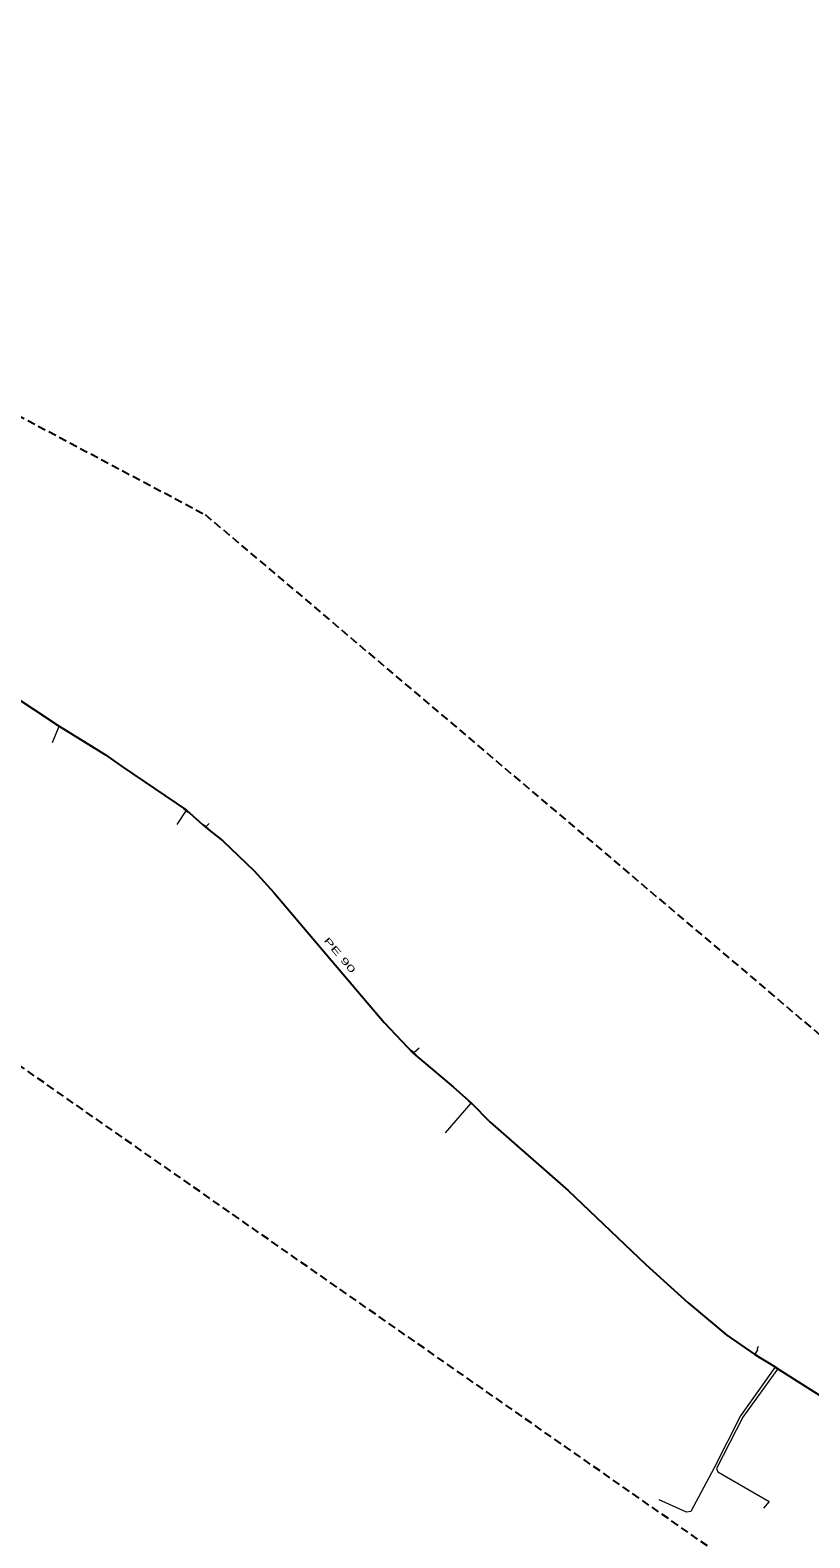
# Model space of a CAD drawing. Extents: x -692311 to -690519, y -971696 to -970899.
# Drawn here: x -692193.2 to -692075.2, y -971126.7 to -970898.7 of the extents above; entities that cross this region are included whole.
import ezdxf

# ---------------------------------------------------------------- set-up
doc = ezdxf.new("R2010")
doc.units = 0
doc.header["$LTSCALE"] = 0.4
doc.linetypes.add('MEDIUM_DASHED', pattern=[4.5, 3, -1.5])
for name, color, linetype, lineweight in [('1', 7, 'MEDIUM_DASHED', 25), ('13', 7, 'Continuous', 13), ('14', 7, 'Continuous', 13), ('17', 7, 'Continuous', 25), ('34', 7, 'Continuous', 13)]:
    doc.layers.add(name, color=color, linetype=linetype, lineweight=lineweight)

msp = doc.modelspace()

# ---------------------------------------------------------------- linework, layer by layer
at = {"layer": '1'}
msp.add_lwpolyline([(-691377.453, -971285.953), (-691463.283, -971177.096), (-691580.514, -971177.096), (-691632.849, -971177.096), (-691781.481, -971235.711), (-691971.982, -971202.217), (-692089.213, -971128.947), (-692311.114, -970974.035), (-692304.834, -970898.672), (-692166.669, -970971.942), (-691976.169, -971133.134), (-691904.993, -971149.882), (-691798.229, -971170.816), (-691674.718, -971116.387), (-691582.607, -971118.48), (-691415.135, -971114.294)], dxfattribs=at)
at = {"layer": '13'}
for p, q in [((-692188.818, -971003.998), (-692189.8, -971006.44)), ((-692169.574, -971016.731), (-692170.98, -971018.809)), ((-692166.541, -971019.127), (-692166.057, -971018.655)), ((-692135.115, -971053.309), (-692134.278, -971052.609)), ((-692126.47, -971060.966), (-692130.364, -971065.46))]:
    msp.add_line(p, q, dxfattribs=at)
for points in [[(-692083.441, -971098.909), (-692083.039, -971098.25), (-692083.1, -971098.079), (-692082.96, -971097.73)], [(-692080.498, -971100.92), (-692085.68, -971108.26), (-692089.66, -971116.09), (-692093.17, -971122.71), (-692093.87, -971122.829), (-692097.997, -971120.94)], [(-692080.061, -971101.184), (-692085.329, -971108.469), (-692089.329, -971116.19), (-692089.12, -971116.71), (-692081.34, -971121.219), (-692082.195, -971122.19)]]:
    msp.add_lwpolyline(points, dxfattribs=at)
at = {"layer": '14'}
for p, q in [((-692188.77, -971003.92), (-692188.818, -971003.998)), ((-692169.52, -971016.66), (-692169.574, -971016.731)), ((-692166.613, -971019.21), (-692166.541, -971019.127)), ((-692135.199, -971053.39), (-692135.115, -971053.309)), ((-692126.42, -971060.91), (-692126.47, -971060.966)), ((-692083.489, -971098.989), (-692083.441, -971098.909)), ((-692080.449, -971100.84), (-692080.498, -971100.92)), ((-692080.02, -971101.12), (-692080.061, -971101.184))]:
    msp.add_line(p, q, dxfattribs=at)
at = {"layer": '17'}
msp.add_lwpolyline([(-692200.44, -970996.21), (-692188.77, -971003.92), (-692181.73, -971008.289), (-692179.17, -971010.07), (-692169.52, -971016.66), (-692166.613, -971019.21), (-692164.02, -971021.3), (-692159.239, -971025.829), (-692156.289, -971029.1), (-692148.42, -971038.35), (-692139.583, -971048.749), (-692135.199, -971053.39), (-692129.1, -971058.52), (-692126.42, -971060.91), (-692123.559, -971063.84), (-692111.75, -971074.19), (-692100.01, -971085.37), (-692093.62, -971091.149), (-692087.739, -971096.03), (-692083.489, -971098.989), (-692080.449, -971100.84), (-692080.02, -971101.12), (-692073.59, -971105.23)], dxfattribs=at)
at = {"layer": '34'}
for p, q in [((-692188.392, -971004.261), (-692189.242, -971003.733)), ((-692169.176, -971017.034), (-692169.97, -971016.426)), ((-692166.917, -971018.797), (-692166.165, -971019.457)), ((-692135.458, -971052.945), (-692134.772, -971053.672)), ((-692126.096, -971061.298), (-692126.842, -971060.632)), ((-692083.868, -971098.649), (-692083.014, -971099.169)), ((-692080.07, -971101.179), (-692080.924, -971100.659)), ((-692079.641, -971101.456), (-692080.479, -971100.91))]:
    msp.add_line(p, q, dxfattribs=at)

# ---------------------------------------------------------------- texts
at = {"layer": '1', "width": 1.8}
msp.add_text('PE 90 ', height=1, rotation=310, dxfattribs=at).set_placement((-692148.802, -971036.378))

doc.saveas('drawing.dxf')
